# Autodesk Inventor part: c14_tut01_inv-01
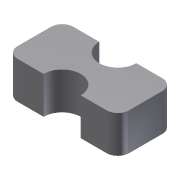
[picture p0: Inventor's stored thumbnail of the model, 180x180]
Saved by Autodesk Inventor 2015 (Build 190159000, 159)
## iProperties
Created: 2010-04
Part Number: c14_tut01_inv-01
Document SubType Name: Modeling
Designer: CADSoft
Density: 1 g/cm^3
Material: Generic
Appearance: Default
Author: CADSoft
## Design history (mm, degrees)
sketch "Sketch1"
  geometry: L1 (33.666, 15.267)-(33.666, -14.733); L2 (-26.334, -14.733)-(-26.334, 15.267); L3 (-26.334, 15.267)-(-6.334, 15.267); L4 (13.666, 15.267)-(33.666, 15.267); L5 (33.666, -14.733)-(13.666, -14.733); L6 (-6.334, -14.733)-(-26.334, -14.733); A1 r 10 centre (3.666, 15.267) between (-6.334, 15.267) and (13.666, 15.267); A2 r 10 centre (3.666, -14.733) between (13.666, -14.733) and (-6.334, -14.733); 1 further point
  constraints: 12 end point, 5 parallel, 4 equal length, 4 point on circle, 2 centre point, 2 horizontal, 2 horizontal alignment, 2 perpendicular, 1 equal radius
  dimensions: "d0" = 60 distance between parallel lines of L1 L2 (= LEN); "d1" = 30 distance of L2.start L2.end (= WID); "d2" = 10 radius of A1 (= RAD)
extrude "Extrusion1" new body sketch "Sketch1" distance "d3" = 20 (= EXT); taper "d4" = 0 deg
fillet "Fillet1" dims "d5" = 6 (= FILLET)
body "Solid1"
other parameters: "LEN" = 60 [user parameter; used in 5 equation terms], "WID" = 30 (= 0.5 x LEN) [user parameter; used in 1 equation term], "RAD" = 10 (= 0.166667 x LEN) [user parameter; used in 1 equation term], "EXT" = 20 (= 0.333333 x LEN) [user parameter; used in 1 equation term], "FILLET" = 6 (= 0.1 x LEN) [user parameter; used in 1 equation term]
